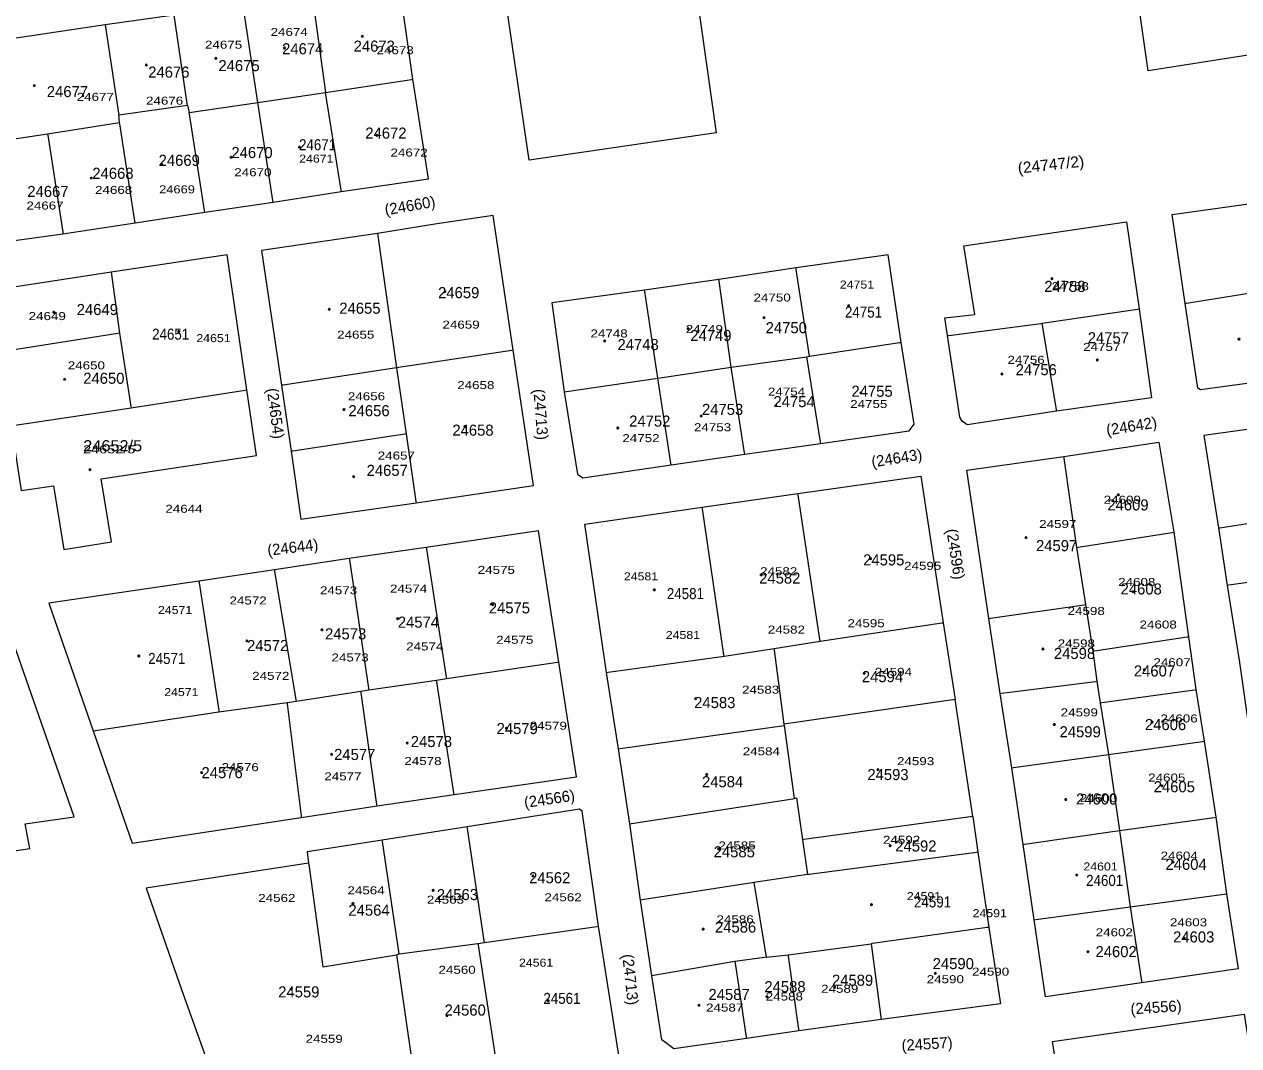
# Model space of a CAD drawing. Extents: x 649608 to 651081, y 237980 to 241202.
# Drawn here: x 649944.8 to 650339.2, y 239612.2 to 239943.9 of the extents above; entities that cross this region are included whole.
import ezdxf

# ---------------------------------------------------------------- set-up
doc = ezdxf.new("R2010")
doc.units = 0
doc.header["$PDMODE"] = 32
doc.header["$PDSIZE"] = 0.5
for name, color, linetype in [('19', 7, 'Continuous'), ('20', 7, 'Continuous'), ('6', 7, 'Continuous')]:
    doc.layers.add(name, color=color, linetype=linetype)
doc.layers.add('3', color=7, linetype='Continuous', lineweight=13)
doc.layers.add('5', color=7, linetype='Continuous', lineweight=13)

msp = doc.modelspace()

# ---------------------------------------------------------------- linework, layer by layer
at = {"layer": '3'}
for p, q in [((650252.873, 239686.595), (650247.189, 239724.65)), ((650339.106, 239637.174), (650307.719, 239632.638)), ((650261.895, 239625.849), (650223.119, 239620.77))]:
    msp.add_line(p, q, dxfattribs=at)
for points in [[(650088.141, 240042.191), (650149.19, 240050.902), (650157.293, 239995.611), (650164.347, 239996.723), (650168.634, 239965.476), (650161.633, 239964.565), (650169.588, 239908.656)], [(650169.588, 239908.656), (650108.765, 239899.717), (650101.708, 239948.509), (650099.051, 239948.199), (650092.508, 239993.558), (650094.984, 239993.566), (650088.141, 240042.191)], [(650071.051, 239926.074), (650066.514, 239958.205), (650038.223, 239953.835), (650015.835, 239950.432), (649993.523, 239946.827), (649971.163, 239943.727)], [(649971.163, 239943.727), (649921.048, 239936.253), (649920.249, 239935.149), (649925.279, 239904.249)], [(650047.782, 239889.543), (650076.097, 239893.661), (650071.051, 239926.074)], [(649925.279, 239904.249), (649930.506, 239872.163), (649957.389, 239875.837), (649980.824, 239879.434), (650003.468, 239882.936), (650025.624, 239886.164), (650047.782, 239889.543)], [(650321.799, 239853.182), (650317.627, 239882.113), (650379.619, 239890.818), (650383.547, 239862.808), (650388.272, 239833.948)], [(650103.636, 239838.072), (650097.133, 239881.791), (650078.222, 239878.996), (650059.513, 239875.971), (650021.87, 239870.404)], [(650253.497, 239849.646), (650249.997, 239871.993), (650302.837, 239879.713), (650306.864, 239851.503)], [(650017.104, 239825.198), (650010.78, 239868.992), (649973.06, 239863.45), (649932.936, 239857.269)], [(650021.87, 239870.404), (650028.373, 239826.684), (650031.55, 239805.228)], [(650229.622, 239840.59), (650225.367, 239868.987), (650195.493, 239864.754), (650170.448, 239861.016), (650146.299, 239857.575), (650116.171, 239853.394), (650120.218, 239824.518)], [(650306.864, 239851.503), (650310.937, 239822.649), (650280.104, 239818.232), (650251.08, 239813.874)], [(650357.01, 239829.262), (650326.82, 239825.19), (650325.994, 239825.713), (650321.799, 239853.182)], [(650244.649, 239842.807), (650243.768, 239848.613), (650253.497, 239849.646)], [(650203.466, 239807.76), (650232.267, 239811.9), (650233.839, 239814.083), (650229.622, 239840.59)], [(650251.08, 239813.874), (650249.419, 239815.061), (650248.661, 239816.302), (650244.649, 239842.807)], [(650072.111, 239788.485), (650110.189, 239794.1), (650103.636, 239838.072)], [(649940.588, 239813.566), (649943.87, 239792.463), (649954.323, 239794.056), (649957.658, 239773.33), (649973.172, 239775.796), (649969.835, 239796.295), (650020.206, 239803.868), (650017.104, 239825.198)], [(650120.218, 239824.518), (650124.536, 239797.809), (650126.239, 239796.613), (650154.887, 239800.83), (650178.806, 239804.272), (650203.466, 239807.76)], [(650359.246, 239814.696), (650327.911, 239810.334), (650332.626, 239780.357), (650335.48, 239761.64), (650339.366, 239737.428), (650342.823, 239713.047), (650346.63, 239688.414), (650350.01, 239663.76), (650350.962, 239657.72), (650413.463, 239667.216)], [(650282.413, 239803.517), (650313.349, 239808.156), (650318.121, 239778.922), (650322.978, 239745.021), (650325.342, 239727.848), (650327.987, 239711.119), (650331.818, 239686.387), (650335.297, 239661.558), (650339.106, 239637.174)], [(650031.55, 239805.228), (650034.673, 239783.168), (650072.111, 239788.485)], [(650258.124, 239750.937), (650250.978, 239799.106), (650282.413, 239803.517)], [(650196.109, 239791.571), (650236.025, 239797.148), (650243.294, 239749.565), (650247.189, 239724.65)], [(650133.916, 239733.418), (650126.855, 239781.579), (650165.034, 239787.068), (650196.109, 239791.571)], [(650118.492, 239736.801), (650111.879, 239779.412), (650075.385, 239773.963), (650050.368, 239770.477), (650026.063, 239766.76), (650001.555, 239763.069)], [(650001.555, 239763.069), (649952.871, 239755.888), (649967.227, 239714.434), (649979.906, 239678.036)], [(649887.601, 239726.78), (649897.69, 239677.034), (649913.663, 239679.422), (649914.76, 239671.546), (649946.602, 239676.221), (649945.098, 239684.275), (649961.019, 239686.562), (649943.929, 239735.574), (649937.717, 239753.671), (649883.998, 239745.591)], [(650307.719, 239632.638), (650276.533, 239628.076), (650272.83, 239653.105), (650269.223, 239677.587), (650265.569, 239702.492), (650261.783, 239726.603), (650258.124, 239750.937)], [(650084.431, 239693.788), (650124.17, 239699.543), (650118.492, 239736.801)], [(650179.344, 239614.539), (650155.782, 239611.169), (650151.895, 239614.146), (650148.688, 239634.921), (650144.994, 239659.482), (650141.507, 239684.319), (650137.863, 239708.628), (650133.916, 239733.418)], [(649979.906, 239678.036), (650034.801, 239686.335), (650059.438, 239690.075), (650084.431, 239693.788)], [(650131.305, 239651.053), (650126.009, 239688.429), (650125.183, 239688.977), (650088.677, 239683.294), (650061.075, 239678.994)], [(650252.873, 239686.595), (650254.547, 239675.049), (650258.09, 239650.631), (650261.895, 239625.849)], [(650061.075, 239678.994), (650036.668, 239675.176), (650037.18, 239671.542)], [(650037.18, 239671.542), (649984.431, 239663.354), (649995.856, 239630.494), (650010.549, 239589.669)], [(650098.716, 239602.658), (650137.995, 239608.441), (650131.305, 239651.053)], [(650284.846, 239575.429), (650278.795, 239613.56), (650341.039, 239622.462), (650346.869, 239584.804), (650352.295, 239546.902), (650358.829, 239503.479)], [(650223.119, 239620.77), (650196.364, 239617.045), (650179.344, 239614.539)]]:
    msp.add_lwpolyline(points, dxfattribs=at)
msp.add_lwpolyline([(650379.366, 240006.183), (650386.357, 239955.842), (650374.029, 239938.824), (650309.84, 239928.724), (650300.505, 239993.965)], close=True, dxfattribs=at)
at = {"layer": '5'}
for p, q in [((649973.06, 239863.45), (649975.763, 239843.561)), ((650247.189, 239724.65), (650191.531, 239716.658)), ((650304.039, 239657.369), (650335.297, 239661.558))]:
    msp.add_line(p, q, dxfattribs=at)
for points in [[(650038.223, 239953.835), (650038.293, 239953.335), (650042.709, 239921.779)], [(650020.705, 239918.5), (650015.911, 239949.932), (650015.835, 239950.432)], [(649997.799, 239917.622), (649997.726, 239918.122), (649993.523, 239946.827)], [(649971.163, 239943.727), (649975.466, 239915.022), (649975.541, 239914.522)], [(650042.709, 239921.779), (650070.551, 239925.998), (650071.051, 239926.074)], [(649925.279, 239904.249), (649925.779, 239904.325), (649952.395, 239908.351), (649975.754, 239912.049), (649975.541, 239914.522), (649997.799, 239917.622), (649998.37, 239915.198), (650020.705, 239918.5), (650042.709, 239921.779)], [(650025.624, 239886.164), (650025.548, 239886.664), (650020.705, 239918.5)], [(650047.782, 239889.543), (650047.703, 239890.043), (650042.709, 239921.779)], [(650003.468, 239882.936), (650003.389, 239883.436), (649998.449, 239914.698), (649998.37, 239915.198)], [(649980.824, 239879.434), (649980.746, 239879.934), (649975.832, 239911.549), (649975.754, 239912.049)], [(649952.395, 239908.351), (649952.472, 239907.851), (649957.312, 239876.337), (649957.389, 239875.837)], [(650059.513, 239875.971), (650065.762, 239832.38), (650068.914, 239810.874)], [(650199.874, 239836.078), (650195.569, 239864.254), (650195.493, 239864.754)], [(650174.422, 239832.545), (650170.518, 239860.516), (650170.448, 239861.016)], [(650150.63, 239829.026), (650146.375, 239857.075), (650146.299, 239857.575)], [(650352.561, 239858.096), (650322.299, 239853.262), (650321.799, 239853.182)], [(650275.451, 239846.819), (650306.364, 239851.428), (650306.864, 239851.503)], [(649975.763, 239843.561), (649975.263, 239843.482), (649936.7, 239837.404), (649936.2, 239837.325)], [(649975.763, 239843.561), (649979.457, 239819.802), (649979.535, 239819.302)], [(650244.649, 239842.807), (650245.149, 239842.872), (650274.951, 239846.754), (650275.451, 239846.819)], [(650280.104, 239818.232), (650280.023, 239818.732), (650275.451, 239846.819)], [(650199.874, 239836.078), (650229.122, 239840.514), (650229.622, 239840.59)], [(650103.636, 239838.072), (650103.136, 239837.997), (650065.762, 239832.38)], [(650120.218, 239824.518), (650150.63, 239829.026), (650174.422, 239832.545), (650199.031, 239835.907), (650199.874, 239836.078)], [(650203.466, 239807.76), (650203.387, 239808.26), (650199.031, 239835.907)], [(650065.762, 239832.38), (650028.873, 239826.76), (650028.373, 239826.684)], [(650178.806, 239804.272), (650178.728, 239804.772), (650174.422, 239832.545)], [(650154.887, 239800.83), (650154.812, 239801.33), (650150.63, 239829.026)], [(649979.535, 239819.302), (650016.604, 239825.12), (650017.104, 239825.198)], [(649940.588, 239813.566), (649941.088, 239813.64), (649979.535, 239819.302)], [(650068.914, 239810.874), (650068.414, 239810.798), (650032.05, 239805.304), (650031.55, 239805.228)], [(650068.914, 239810.874), (650072.04, 239788.985), (650072.111, 239788.485)], [(650282.413, 239803.517), (650282.484, 239803.017), (650286.605, 239774.016), (650289.511, 239755.497), (650291.867, 239740.359), (650293.214, 239730.567), (650294.234, 239723.558), (650296.903, 239706.78), (650300.559, 239682.123), (650304.039, 239657.369)], [(650203.324, 239743.585), (650203.249, 239744.085), (650196.184, 239791.071), (650196.109, 239791.571)], [(650172.093, 239738.679), (650172.02, 239739.179), (650165.107, 239786.568), (650165.034, 239787.068)], [(650332.626, 239780.357), (650333.126, 239780.435), (650358.508, 239784.395), (650363.69, 239785.242)], [(650358.508, 239784.395), (650358.588, 239783.895), (650361.534, 239765.379), (650335.98, 239761.712), (650335.48, 239761.64)], [(650286.605, 239774.016), (650287.105, 239774.094), (650317.621, 239778.844), (650318.121, 239778.922)], [(650075.385, 239773.963), (650075.462, 239773.463), (650081.845, 239731.928), (650081.922, 239731.428)], [(650050.368, 239770.477), (650050.442, 239769.977), (650056.65, 239728.267), (650056.724, 239727.767)], [(650026.063, 239766.76), (650026.146, 239766.26), (650033.026, 239724.571), (650033.109, 239724.071)], [(650001.555, 239763.069), (650001.632, 239762.569), (650007.989, 239721.085), (650008.066, 239720.585)], [(650258.124, 239750.937), (650258.624, 239751.01), (650289.011, 239755.424), (650289.511, 239755.497)], [(650203.324, 239743.585), (650242.794, 239749.49), (650243.294, 239749.565)], [(650291.867, 239740.359), (650292.367, 239740.434), (650322.478, 239744.946), (650322.978, 239745.021)], [(650133.916, 239733.418), (650134.416, 239733.487), (650172.093, 239738.679), (650188.322, 239741.166), (650203.324, 239743.585)], [(650188.322, 239741.166), (650188.387, 239740.666), (650191.531, 239716.658), (650191.589, 239716.243), (650194.917, 239692.476)], [(650081.922, 239731.428), (650117.992, 239736.728), (650118.492, 239736.801)], [(649967.227, 239714.434), (650008.066, 239720.585), (650030.171, 239723.712), (650033.109, 239724.071), (650054.169, 239727.356), (650056.724, 239727.767), (650078.727, 239730.92), (650081.922, 239731.428)], [(650084.431, 239693.788), (650084.354, 239694.288), (650078.804, 239730.42), (650078.727, 239730.92)], [(650261.783, 239726.603), (650262.283, 239726.666), (650292.714, 239730.504), (650293.214, 239730.567)], [(650059.438, 239690.075), (650059.367, 239690.575), (650054.24, 239726.856), (650054.169, 239727.356)], [(650294.234, 239723.558), (650294.734, 239723.627), (650324.842, 239727.779), (650325.342, 239727.848)], [(650030.171, 239723.712), (650030.233, 239723.212), (650034.739, 239686.835), (650034.801, 239686.335)], [(650137.863, 239708.628), (650138.363, 239708.699), (650191.589, 239716.243)], [(650296.903, 239706.78), (650327.487, 239711.049), (650327.987, 239711.119)], [(650265.569, 239702.492), (650266.069, 239702.56), (650296.903, 239706.78)], [(650141.507, 239684.319), (650142.007, 239684.395), (650194.417, 239692.4), (650194.917, 239692.476)], [(650194.917, 239692.476), (650195.629, 239692.693), (650197.538, 239679.12), (650199.225, 239667.786), (650181.771, 239665.182), (650185.722, 239640.972), (650192.876, 239641.781), (650219.834, 239645.303), (650223.119, 239620.77)], [(650252.873, 239686.595), (650198.038, 239679.188), (650197.538, 239679.12)], [(650300.559, 239682.123), (650331.318, 239686.319), (650331.818, 239686.387)], [(650094.302, 239645.733), (650094.227, 239646.233), (650088.752, 239682.794), (650088.677, 239683.294)], [(650269.223, 239677.587), (650269.723, 239677.659), (650300.559, 239682.123)], [(650066.576, 239642.039), (650061.149, 239678.494), (650061.075, 239678.994)], [(650254.547, 239675.049), (650254.047, 239674.983), (650199.725, 239667.852), (650199.225, 239667.786)], [(650037.18, 239671.542), (650037.249, 239671.042), (650041.835, 239637.821), (650065.68, 239641.692), (650066.576, 239642.039), (650092.155, 239645.42), (650094.302, 239645.733)], [(650181.771, 239665.182), (650181.271, 239665.105), (650145.494, 239659.559), (650144.994, 239659.482)], [(650272.83, 239653.105), (650273.33, 239653.173), (650304.039, 239657.369)], [(650304.039, 239657.369), (650307.645, 239633.138), (650307.719, 239632.638)], [(650094.302, 239645.733), (650130.805, 239650.981), (650131.305, 239651.053)], [(650258.09, 239650.631), (650257.59, 239650.561), (650220.334, 239645.373), (650219.834, 239645.303)], [(650092.155, 239645.42), (650092.232, 239644.92), (650098.639, 239603.158), (650098.716, 239602.658)], [(650065.68, 239641.692), (650071.884, 239599.004), (650071.957, 239598.504)], [(650175.602, 239639.529), (650149.188, 239635.007), (650148.688, 239634.921)], [(650185.722, 239640.972), (650185.222, 239640.901), (650175.602, 239639.529)], [(650175.602, 239639.529), (650175.677, 239639.029), (650179.269, 239615.039), (650179.344, 239614.539)], [(650192.876, 239641.781), (650192.947, 239641.281), (650196.293, 239617.545), (650196.364, 239617.045)]]:
    msp.add_lwpolyline(points, dxfattribs=at)
at = {"layer": '6'}
for p in [(650054.623, 239939.992), (650029.353, 239936.167), (649984.504, 239930.674), (650007.048, 239932.815), (649948.094, 239923.988), (650059.401, 239907.808), (650034.213, 239903.971), (649989.43, 239898.528), (650012.034, 239900.718), (649966.588, 239893.943), (650278.575, 239861.26), (650081.514, 239857.085), (650043.877, 239851.327), (650212.596, 239852.532), (649954.449, 239850.387), (650185.064, 239848.649), (649995.026, 239844.147), (650160.442, 239845.021), (650133.354, 239841.046), (650339.33, 239841.643), (650293.304, 239834.867), (649957.957, 239828.563), (650262.334, 239830.346), (650216.556, 239824.175), (650188.938, 239820.089), (650048.646, 239818.804), (650164.687, 239816.687), (650087.946, 239813.278), (650137.593, 239812.819), (649966.198, 239799.264), (650051.802, 239797.021), (650300.157, 239791.086), (650270.186, 239777.227), (650219.707, 239770.366), (650184.16, 239765.125), (650149.465, 239760.243), (650304.872, 239759.64), (650096.919, 239755.42), (650066.111, 239750.865), (650041.55, 239747.274), (650017.201, 239743.672), (650275.685, 239741.05), (649982.044, 239738.751), (650217.621, 239733.111), (650308.579, 239734.289), (650162.862, 239724.897), (650311.117, 239717.314), (650101.449, 239715.294), (650279.359, 239716.529), (650069.208, 239710.497), (650044.664, 239706.845), (650222.094, 239701.885), (650002.475, 239700.874), (650166.469, 239700.281), (650314.321, 239696.621), (650283.074, 239692.183), (650170.326, 239676.087), (650226.031, 239677.19), (650317.925, 239671.878), (650110.03, 239667.355), (650286.646, 239667.614), (650077.636, 239662.666), (650051.566, 239658.407), (650219.98, 239658.01), (650165.326, 239650.051), (650321.562, 239647.098), (650290.292, 239642.722), (650240.751, 239635.7), (650031.554, 239630.605), (650208.049, 239631.174), (650115.054, 239626.855), (650186.051, 239628.16), (650163.945, 239625.349), (650082.151, 239621.962)]:
    msp.add_point(p, dxfattribs=at)

# ---------------------------------------------------------------- texts
at = {"layer": '19'}
for s, p in [('24673', (650051.796, 239934.988)), ('24674', (650028.577, 239934.146)), ('24676', (649985.097, 239926.563)), ('24675', (650007.893, 239928.669)), ('24677', (649952.17, 239920.244)), ('24672', (650055.595, 239906.764)), ('24670', (650012.113, 239900.445)), ('24669', (649988.473, 239897.918)), ('24668', (649966.944, 239893.705)), ('24667', (649945.837, 239887.808)), ('24659', (650079.235, 239854.951)), ('24649', (649961.878, 239849.475)), ('24655', (650047.151, 239849.896)), ('24750', (650185.612, 239843.578)), ('24749', (650161.129, 239841.05)), ('24748', (650137.488, 239838.101)), ('24650', (649963.988, 239827.149)), ('24755', (650213.474, 239822.936)), ('24656', (650050.107, 239816.617)), ('24753', (650164.928, 239817.039)), ('24754', (650188.145, 239819.566)), ('24752', (650141.288, 239813.247)), ('24658', (650083.878, 239810.299)), ('24657', (650056.017, 239797.24)), ('24595', (650217.274, 239768.173)), ('24582', (650183.502, 239762.275)), ('24575', (650095.697, 239752.586)), ('24574', (650066.146, 239747.952)), ('24573', (650042.507, 239744.161)), ('24572', (650017.178, 239740.369)), ('24594', (650216.851, 239730.26)), ('24583', (650162.395, 239721.835)), ('24579', (650098.231, 239713.409)), ('24578', (650070.368, 239709.197)), ('24577', (650045.463, 239704.984)), ('24576', (650002.404, 239699.086)), ('24584', (650164.928, 239696.138)), ('24585', (650168.727, 239673.39)), ('24562', (650108.784, 239664.966)), ('24563', (650078.811, 239659.489)), ('24564', (650050.105, 239654.434)), ('24586', (650169.15, 239648.958)), ('24589', (650207.143, 239631.686)), ('24559', (650027.31, 239627.895)), ('24587', (650167.04, 239627.053)), ('24588', (650185.191, 239629.58)), ('24560', (650081.343, 239621.998))]:
    msp.add_text(s, height=3.6, dxfattribs=at).set_placement(p)
for s, width, p in [('24671', 0.9, (650034.066, 239902.973)), ('24751', 0.9, (650211.364, 239848.633)), ('24651', 0.9, (649986.363, 239841.471)), ('24652/5', 1.1, (649963.987, 239805.243)), ('24581', 0.9, (650153.53, 239757.22)), ('24571', 0.9, (649985.095, 239736.157)), ('24561', 0.9, (650113.427, 239625.789))]:
    msp.add_text(s, height=3.6, dxfattribs=dict(at, width=width)).set_placement(p)
for s, rotation, width, p in [('(24747/2)', 6.161, 1.05, (650267.682, 239895.395)), ('24601', 359.954, 0.9, (650289.678, 239664.089)), ('24591', 359.954, 0.9, (650233.79, 239657.127))]:
    msp.add_text(s, height=3.6, rotation=rotation, dxfattribs=dict(at, width=width)).set_placement(p)
for s, rotation, p in [('(24660)', 9.85, (650062.221, 239881.829)), ('24758', 359.954, (650276.083, 239856.992)), ('24757', 359.954, (650290.199, 239840.297)), ('24756', 359.954, (650266.785, 239829.941)), ('(24654)', 277.567, (650023.585, 239825.534)), ('(24713)', 274.523, (650110.157, 239825.344)), ('(24642)', 9.083, (650296.507, 239810.336)), ('(24643)', 8.987, (650220.259, 239799.98)), ('24609', 359.954, (650296.578, 239786.038)), ('(24644)', 6.827, (650024.01, 239771.301)), ('(24596)', 278.691, (650244.273, 239779.79)), ('24597', 359.954, (650273.403, 239772.815)), ('24608', 359.954, (650300.873, 239758.742)), ('24598', 359.954, (650279.218, 239737.822)), ('24607', 359.954, (650305.182, 239732.111)), ('24606', 359.954, (650308.786, 239714.701)), ('24599', 359.954, (650281.052, 239712.367)), ('24593', 359.954, (650218.635, 239698.477)), ('24605', 359.954, (650311.629, 239694.521)), ('(24566)', 8.446, (650107.437, 239689.388)), ('24600', 359.954, (650286.409, 239690.549)), ('24592', 359.954, (650227.695, 239675.285)), ('24604', 359.954, (650315.454, 239669.328)), ('24603', 359.954, (650317.926, 239645.744)), ('24602', 359.954, (650292.724, 239640.988)), ('(24713)', 276.184, (650139.025, 239641.772)), ('24590', 359.954, (650239.847, 239637.078)), ('(24556)', 3.719, (650304.217, 239622.369)), ('(24557)', 3.53, (650229.852, 239610.526))]:
    msp.add_text(s, height=3.6, rotation=rotation, dxfattribs=at).set_placement(p)
at = {"layer": '20'}
for s, width, p in [('24674', 1.25, (650024.835, 239940.096)), ('24675', 1.25, (650003.534, 239935.963)), ('24673', 1.25, (650059.237, 239934.166)), ('24677', 1.25, (649961.869, 239919.029)), ('24676', 1.25, (649984.369, 239917.795)), ('24672', 1.25, (650063.773, 239900.937)), ('24671', 1.15, (650034.125, 239898.96)), ('24670', 1.25, (650013.043, 239894.545)), ('24668', 1.25, (649967.815, 239888.813)), ('24669', 1.2, (649988.642, 239888.991)), ('24667', 1.25, (649945.548, 239883.73)), ('24751', 1.15, (650209.711, 239858.074)), ('24758', 1.25, (650278.494, 239857.543)), ('24750', 1.25, (650181.68, 239853.861)), ('24649', 1.25, (649946.26, 239847.837)), ('24659', 1.25, (650080.647, 239845.067)), ('24651', 1.15, (650000.731, 239840.677)), ('24655', 1.25, (650046.444, 239841.811)), ('24748', 1.25, (650128.721, 239842.192)), ('24749', 1.25, (650159.654, 239843.628)), ('24757', 1.25, (650288.716, 239837.831)), ('24756', 1.25, (650264.149, 239833.634)), ('24650', 1.25, (649958.968, 239831.846)), ('24658', 1.25, (650085.435, 239825.436)), ('24656', 1.25, (650049.933, 239821.798)), ('24754', 1.25, (650186.345, 239823.31)), ('24755', 1.25, (650213.052, 239819.289)), ('24753', 1.25, (650162.326, 239811.75)), ('24752', 1.25, (650139.071, 239808.207)), ('24652/5', 1.35, (649963.945, 239804.575)), ('24657', 1.25, (650059.623, 239802.551)), ('24609', 1.25, (650295.384, 239788.21)), ('24644', 1.25, (649990.67, 239785.268)), ('24597', 1.25, (650274.431, 239780.325)), ('24595', 1.25, (650230.566, 239766.749)), ('24575', 1.25, (650092.107, 239765.422)), ('24581', 1.15, (650139.57, 239763.327)), ('24582', 1.25, (650183.799, 239764.985)), ('24573', 1.25, (650040.868, 239758.805)), ('24574', 1.25, (650063.607, 239759.345)), ('24608', 1.25, (650300.091, 239761.503)), ('24572', 1.25, (650011.489, 239755.49)), ('24571', 1.15, (649988.257, 239752.396)), ('24598', 1.25, (650283.671, 239752.092)), ('24582', 1.25, (650186.296, 239746.038)), ('24595', 1.25, (650212.193, 239748.107)), ('24608', 1.25, (650307.042, 239747.684)), ('24575', 1.25, (650098.085, 239742.732)), ('24581', 1.15, (650153.184, 239744.291)), ('24574', 1.25, (650068.856, 239740.57)), ('24598', 1.25, (650280.465, 239741.548)), ('24573', 1.25, (650044.603, 239736.983)), ('24607', 1.25, (650311.545, 239735.443)), ('24572', 1.25, (650018.856, 239731.017)), ('24594', 1.25, (650221.052, 239732.316)), ('24583', 1.25, (650177.928, 239726.526)), ('24571', 1.15, (649990.299, 239725.744)), ('24599', 1.25, (650281.425, 239719.152)), ('24579', 1.25, (650108.988, 239714.826)), ('24606', 1.25, (650313.829, 239717.18)), ('24584', 1.25, (650178.168, 239706.519)), ('24578', 1.25, (650068.274, 239703.365)), ('24593', 1.25, (650228.264, 239703.323)), ('24576', 1.25, (650008.915, 239701.375)), ('24577', 1.25, (650042.28, 239698.388)), ('24605', 1.25, (650309.841, 239697.998)), ('24600', 1.25, (650287.655, 239691.308)), ('24585', 1.25, (650170.289, 239675.939)), ('24592', 1.25, (650223.716, 239677.791)), ('24604', 1.25, (650313.87, 239672.646)), ('24601', 1.15, (650288.805, 239669.125)), ('24564', 1.25, (650049.795, 239661.377)), ('24591', 1.15, (650231.469, 239659.503)), ('24562', 1.25, (650020.821, 239658.901)), ('24563', 1.25, (650075.576, 239658.343)), ('24562', 1.25, (650113.781, 239659.125)), ('24586', 1.25, (650169.65, 239651.961)), ('24591', 1.15, (650252.819, 239653.96)), ('24602', 1.25, (650292.784, 239647.747)), ('24603', 1.25, (650316.896, 239650.988)), ('24560', 1.25, (650079.361, 239635.574)), ('24561', 1.15, (650105.506, 239637.887)), ('24590', 1.25, (650237.911, 239632.515)), ('24590', 1.25, (650252.618, 239634.971)), ('24589', 1.25, (650203.621, 239629.409)), ('24588', 1.25, (650185.638, 239626.9)), ('24587', 1.25, (650166.261, 239623.308)), ('24559', 1.25, (650036.199, 239613.163))]:
    msp.add_text(s, height=2.6, dxfattribs=dict(at, width=width)).set_placement(p)

doc.saveas('drawing.dxf')
